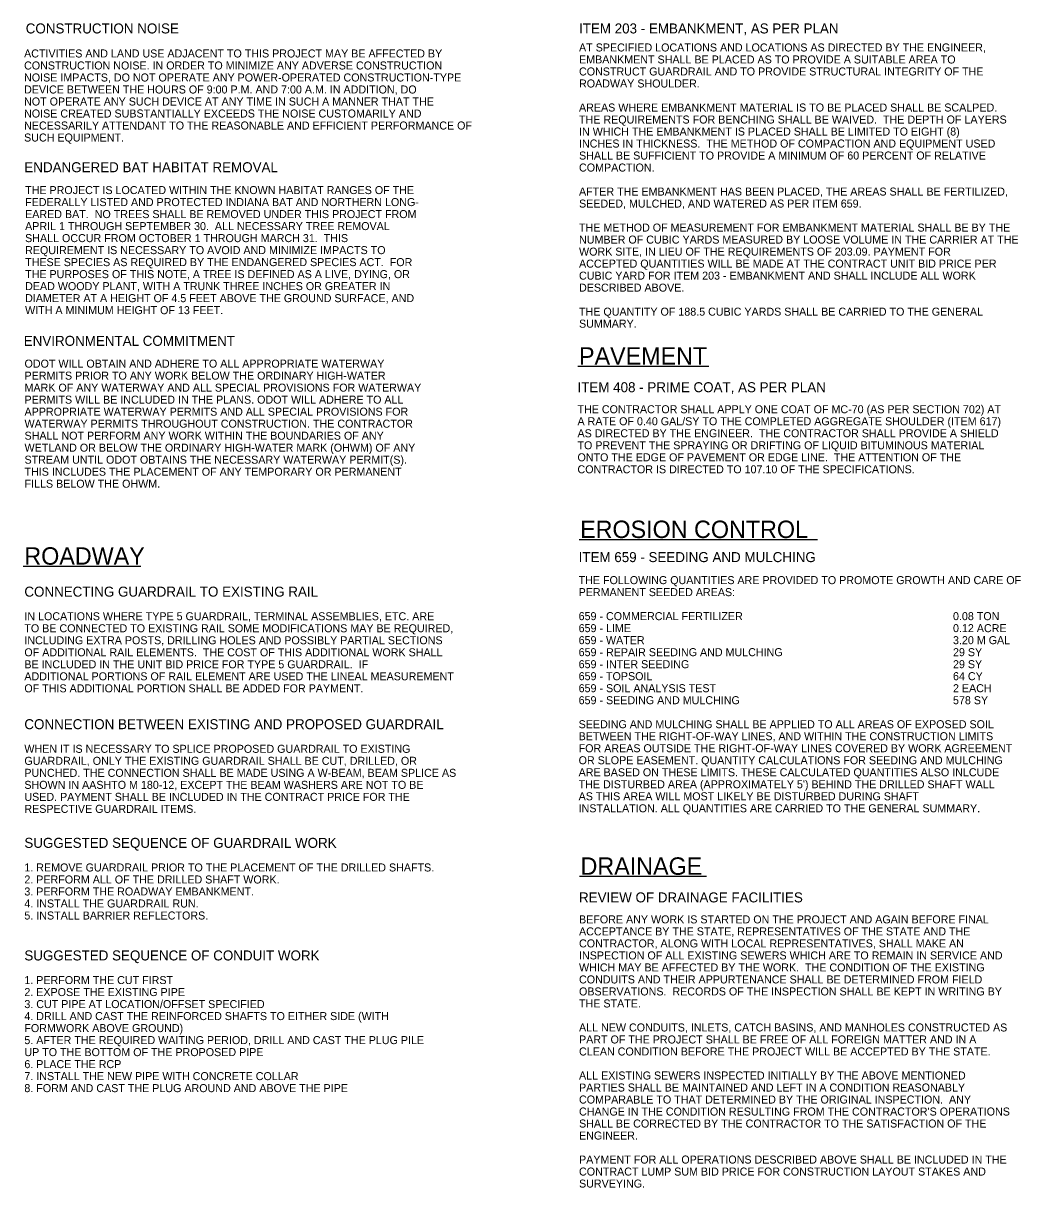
# Model space of a CAD drawing. Extents: x 0 to 43.5, y 0 to 44.1.
# Drawn here: x 12.78 to 30.22, y 23.75 to 44.11 of the extents above; entities that cross this region are included whole.
import ezdxf

# ---------------------------------------------------------------- set-up
doc = ezdxf.new("R2010")
doc.units = 0
doc.layers.add('Default', color=7, linetype='Continuous')
doc.layers.add('TX_P_1', color=7, linetype='Continuous')

msp = doc.modelspace()

# ---------------------------------------------------------------- linework, layer by layer
at = {"layer": 'Default'}
for p, q in [((22.481, 38.118), (24.771, 38.118)), ((22.5, 35.085), (26.668, 35.085)), ((12.781, 34.619), (14.836, 34.619)), ((22.508, 29.196), (24.729, 29.196))]:
    msp.add_line(p, q, dxfattribs=at)

# ---------------------------------------------------------------- texts
at = {"layer": 'TX_P_1'}
for s, height, p in [('CONSTRUCTION NOISE', 0.175, (12.824, 43.934)), ('ITEM 203 - EMBANKMENT, AS PER PLAN', 0.175, (22.5, 43.934)), ('ACTIVITIES AND LAND USE ADJACENT TO THIS PROJECT MAY BE AFFECTED BY ', 0.14, (12.795, 43.514)), ('AT SPECIFIED LOCATIONS AND LOCATIONS AS DIRECTED BY THE ENGINEER, ', 0.14, (22.5, 43.619)), ('CONSTRUCTION NOISE. IN ORDER TO MINIMIZE ANY ADVERSE CONSTRUCTION ', 0.14, (12.795, 43.304)), ('EMBANKMENT SHALL BE PLACED AS TO PROVIDE A SUITABLE AREA TO ', 0.14, (22.5, 43.409)), ('NOISE IMPACTS, DO NOT OPERATE ANY POWER-OPERATED CONSTRUCTION-TYPE ', 0.14, (12.795, 43.094)), ('CONSTRUCT GUARDRAIL AND TO PROVIDE STRUCTURAL INTEGRITY OF THE ', 0.14, (22.5, 43.199)), ('DEVICE BETWEEN THE HOURS OF 9:00 P.M. AND 7:00 A.M. IN ADDITION, DO ', 0.14, (12.795, 42.884)), ('ROADWAY SHOULDER.', 0.14, (22.5, 42.989)), ('NOT OPERATE ANY SUCH DEVICE AT ANY TIME IN SUCH A MANNER THAT THE ', 0.14, (12.795, 42.674)), ('NOISE CREATED SUBSTANTIALLY EXCEEDS THE NOISE CUSTOMARILY AND ', 0.14, (12.795, 42.464)), ('AREAS WHERE EMBANKMENT MATERIAL IS TO BE PLACED SHALL BE SCALPED. ', 0.14, (22.5, 42.569)), ('NECESSARILY ATTENDANT TO THE REASONABLE AND EFFICIENT PERFORMANCE OF ', 0.14, (12.795, 42.254)), ('THE REQUIREMENTS FOR BENCHING SHALL BE WAIVED.  THE DEPTH OF LAYERS ', 0.14, (22.5, 42.359)), ('SUCH EQUIPMENT.', 0.14, (12.795, 42.044)), ('IN WHICH THE EMBANKMENT IS PLACED SHALL BE LIMITED TO EIGHT (8) ', 0.14, (22.5, 42.149)), ('INCHES IN THICKNESS.  THE METHOD OF COMPACTION AND EQUIPMENT USED ', 0.14, (22.5, 41.939)), ('SHALL BE SUFFICIENT TO PROVIDE A MINIMUM OF 60 PERCENT OF RELATIVE ', 0.14, (22.5, 41.729)), ('ENDANGERED BAT HABITAT REMOVAL', 0.175, (12.8, 41.507)), ('COMPACTION.', 0.14, (22.5, 41.519)), ('THE PROJECT IS LOCATED WITHIN THE KNOWN HABITAT RANGES OF THE ', 0.14, (12.813, 41.125)), ('AFTER THE EMBANKMENT HAS BEEN PLACED, THE AREAS SHALL BE FERTILIZED, ', 0.14, (22.5, 41.099)), ('FEDERALLY LISTED AND PROTECTED INDIANA BAT AND NORTHERN LONG-', 0.14, (12.813, 40.915)), ('SEEDED, MULCHED, AND WATERED AS PER ITEM 659. ', 0.14, (22.5, 40.889)), ('EARED BAT.  NO TREES SHALL BE REMOVED UNDER THIS PROJECT FROM ', 0.14, (12.813, 40.705)), ('APRIL 1 THROUGH SEPTEMBER 30.  ALL NECESSARY TREE REMOVAL ', 0.14, (12.813, 40.495)), ('THE METHOD OF MEASUREMENT FOR EMBANKMENT MATERIAL SHALL BE BY THE ', 0.14, (22.5, 40.469)), ('SHALL OCCUR FROM OCTOBER 1 THROUGH MARCH 31.  THIS ', 0.14, (12.813, 40.285)), ('NUMBER OF CUBIC YARDS MEASURED BY LOOSE VOLUME IN THE CARRIER AT THE ', 0.14, (22.5, 40.259)), ('REQUIREMENT IS NECESSARY TO AVOID AND MINIMIZE IMPACTS TO ', 0.14, (12.813, 40.075)), ('WORK SITE, IN LIEU OF THE REQUIREMENTS OF 203.09. PAYMENT FOR ', 0.14, (22.5, 40.049)), ('THESE SPECIES AS REQUIRED BY THE ENDANGERED SPECIES ACT.  FOR ', 0.14, (12.813, 39.865)), ('ACCEPTED QUANTITIES WILL BE MADE AT THE CONTRACT UNIT BID PRICE PER ', 0.14, (22.5, 39.839)), ('THE PURPOSES OF THIS NOTE, A TREE IS DEFINED AS A LIVE, DYING, OR ', 0.14, (12.813, 39.655)), ('CUBIC YARD FOR ITEM 203 - EMBANKMENT AND SHALL INCLUDE ALL WORK ', 0.14, (22.5, 39.629)), ('DEAD WOODY PLANT, WITH A TRUNK THREE INCHES OR GREATER IN ', 0.14, (12.813, 39.445)), ('DESCRIBED ABOVE.', 0.14, (22.5, 39.419)), ('DIAMETER AT A HEIGHT OF 4.5 FEET ABOVE THE GROUND SURFACE, AND ', 0.14, (12.813, 39.235)), ('WITH A MINIMUM HEIGHT OF 13 FEET.', 0.14, (12.813, 39.025)), ('THE QUANTITY OF 188.5 CUBIC YARDS SHALL BE CARRIED TO THE GENERAL ', 0.14, (22.5, 38.999)), ('SUMMARY.', 0.14, (22.5, 38.789)), ('ENVIRONMENTAL COMMITMENT', 0.175, (12.79, 38.471)), ('PAVEMENT', 0.3047, (22.5, 38.142)), ('ODOT WILL OBTAIN AND ADHERE TO ALL APPROPRIATE WATERWAY ', 0.14, (12.803, 38.09)), ('PERMITS PRIOR TO ANY WORK BELOW THE ORDINARY HIGH-WATER ', 0.14, (12.803, 37.88)), ('MARK OF ANY WATERWAY AND ALL SPECIAL PROVISIONS FOR WATERWAY ', 0.14, (12.803, 37.67)), ('ITEM 408 - PRIME COAT, AS PER PLAN', 0.175, (22.473, 37.66)), ('PERMITS WILL BE INCLUDED IN THE PLANS. ODOT WILL ADHERE TO ALL ', 0.14, (12.803, 37.46)), ('APPROPRIATE WATERWAY PERMITS AND ALL SPECIAL PROVISIONS FOR ', 0.14, (12.803, 37.25)), ('THE CONTRACTOR SHALL APPLY ONE COAT OF MC-70 (AS PER SECTION 702) AT ', 0.14, (22.473, 37.292)), ('WATERWAY PERMITS THROUGHOUT CONSTRUCTION. THE CONTRACTOR ', 0.14, (12.803, 37.04)), ('A RATE OF 0.40 GAL/SY TO THE COMPLETED AGGREGATE SHOULDER (ITEM 617) ', 0.14, (22.473, 37.082)), ('SHALL NOT PERFORM ANY WORK WITHIN THE BOUNDARIES OF ANY ', 0.14, (12.803, 36.83)), ('AS DIRECTED BY THE ENGINEER.  THE CONTRACTOR SHALL PROVIDE A SHIELD ', 0.14, (22.473, 36.872)), ('WETLAND OR BELOW THE ORDINARY HIGH-WATER MARK (OHWM) OF ANY ', 0.14, (12.803, 36.62)), ('TO PREVENT THE SPRAYING OR DRIFTING OF LIQUID BITUMINOUS MATERIAL ', 0.14, (22.473, 36.662)), ('STREAM UNTIL ODOT OBTAINS THE NECESSARY WATERWAY PERMIT(S). ', 0.14, (12.803, 36.41)), ('ONTO THE EDGE OF PAVEMENT OR EDGE LINE.  THE ATTENTION OF THE ', 0.14, (22.473, 36.452)), ('THIS INCLUDES THE PLACEMENT OF ANY TEMPORARY OR PERMANENT ', 0.14, (12.803, 36.2)), ('CONTRACTOR IS DIRECTED TO 107.10 OF THE SPECIFICATIONS.', 0.14, (22.473, 36.242)), ('FILLS BELOW THE OHWM.', 0.14, (12.803, 35.99)), ('EROSION CONTROL', 0.30475, (22.519, 35.11)), ('ROADWAY', 0.3047, (12.8, 34.644)), ('ITEM 659 - SEEDING AND MULCHING', 0.175, (22.493, 34.689)), ('THE FOLLOWING QUANTITIES ARE PROVIDED TO PROMOTE GROWTH AND CARE OF ', 0.14, (22.493, 34.304)), ('CONNECTING GUARDRAIL TO EXISTING RAIL', 0.175, (12.8, 34.085)), ('PERMANENT SEEDED AREAS:', 0.14, (22.493, 34.094)), ('IN LOCATIONS WHERE TYPE 5 GUARDRAIL, TERMINAL ASSEMBLIES, ETC. ARE ', 0.14, (12.8, 33.672)), ('659 - COMMERCIAL FERTILIZER', 0.14, (22.493, 33.674)), ('0.08 TON', 0.14, (29.04, 33.674)), ('TO BE CONNECTED TO EXISTING RAIL SOME MODIFICATIONS MAY BE REQUIRED, ', 0.14, (12.8, 33.462)), ('659 - LIME', 0.14, (22.493, 33.464)), ('0.12 ACRE', 0.14, (29.04, 33.464)), ('659 - WATER', 0.14, (22.493, 33.254)), ('3.20 M GAL', 0.14, (29.04, 33.254)), ('INCLUDING EXTRA POSTS, DRILLING HOLES AND POSSIBLY PARTIAL SECTIONS ', 0.14, (12.8, 33.252)), ('OF ADDITIONAL RAIL ELEMENTS.  THE COST OF THIS ADDITIONAL WORK SHALL ', 0.14, (12.8, 33.042)), ('659 - REPAIR SEEDING AND MULCHING', 0.14, (22.493, 33.044)), ('29 SY', 0.14, (29.04, 33.044)), ('BE INCLUDED IN THE UNIT BID PRICE FOR TYPE 5 GUARDRAIL.  IF ', 0.14, (12.8, 32.832)), ('659 - INTER SEEDING', 0.14, (22.493, 32.834)), ('29 SY', 0.14, (29.04, 32.834)), ('ADDITIONAL PORTIONS OF RAIL ELEMENT ARE USED THE LINEAL MEASUREMENT ', 0.14, (12.8, 32.622)), ('659 - TOPSOIL', 0.14, (22.493, 32.624)), ('64 CY', 0.14, (29.04, 32.624)), ('OF THIS ADDITIONAL PORTION SHALL BE ADDED FOR PAYMENT.', 0.14, (12.8, 32.412)), ('659 - SOIL ANALYSIS TEST', 0.14, (22.493, 32.414)), ('2 EACH', 0.14, (29.04, 32.414)), ('659 - SEEDING AND MULCHING', 0.14, (22.493, 32.204)), ('578 SY', 0.14, (29.04, 32.204)), ('CONNECTION BETWEEN EXISTING AND PROPOSED GUARDRAIL', 0.175, (12.8, 31.767)), ('SEEDING AND MULCHING SHALL BE APPLIED TO ALL AREAS OF EXPOSED SOIL ', 0.14, (22.493, 31.784)), ('BETWEEN THE RIGHT-OF-WAY LINES, AND WITHIN THE CONSTRUCTION LIMITS ', 0.14, (22.493, 31.574)), ('WHEN IT IS NECESSARY TO SPLICE PROPOSED GUARDRAIL TO EXISTING ', 0.14, (12.8, 31.354)), ('FOR AREAS OUTSIDE THE RIGHT-OF-WAY LINES COVERED BY WORK AGREEMENT ', 0.14, (22.493, 31.364)), ('GUARDRAIL, ONLY THE EXISTING GUARDRAIL SHALL BE CUT, DRILLED, OR ', 0.14, (12.8, 31.144)), ('OR SLOPE EASEMENT. QUANTITY CALCULATIONS FOR SEEDING AND MULCHING ', 0.14, (22.493, 31.154)), ('PUNCHED. THE CONNECTION SHALL BE MADE USING A W-BEAM, BEAM SPLICE AS ', 0.14, (12.8, 30.934)), ('ARE BASED ON THESE LIMITS. THESE CALCULATED QUANTITIES ALSO INLCUDE ', 0.14, (22.493, 30.944)), ('SHOWN IN AASHTO M 180-12, EXCEPT THE BEAM WASHERS ARE NOT TO BE ', 0.14, (12.8, 30.724)), ("THE DISTURBED AREA (APPROXIMATELY 5') BEHIND THE DRILLED SHAFT WALL ", 0.14, (22.493, 30.734)), ('USED. PAYMENT SHALL BE INCLUDED IN THE CONTRACT PRICE FOR THE ', 0.14, (12.8, 30.514)), ('AS THIS AREA WILL MOST LIKELY BE DISTURBED DURING SHAFT ', 0.14, (22.493, 30.524)), ('RESPECTIVE GUARDRAIL ITEMS.', 0.14, (12.8, 30.304)), ('INSTALLATION. ALL QUANTITIES ARE CARRIED TO THE GENERAL SUMMARY.', 0.14, (22.493, 30.314)), ('SUGGESTED SEQUENCE OF GUARDRAIL WORK', 0.175, (12.8, 29.692)), ('DRAINAGE', 0.3047, (22.527, 29.221)), ('1. REMOVE GUARDRAIL PRIOR TO THE PLACEMENT OF THE DRILLED SHAFTS.', 0.14, (12.8, 29.279)), ('2. PERFORM ALL OF THE DRILLED SHAFT WORK. ', 0.14, (12.8, 29.069)), ('3. PERFORM THE ROADWAY EMBANKMENT.  ', 0.14, (12.8, 28.859)), ('REVIEW OF DRAINAGE FACILITIES', 0.175, (22.5, 28.738)), ('4. INSTALL THE GUARDRAIL RUN. ', 0.14, (12.8, 28.649)), ('5. INSTALL BARRIER REFLECTORS.', 0.14, (12.8, 28.439)), ('BEFORE ANY WORK IS STARTED ON THE PROJECT AND AGAIN BEFORE FINAL ', 0.14, (22.5, 28.371)), ('ACCEPTANCE BY THE STATE, REPRESENTATIVES OF THE STATE AND THE ', 0.14, (22.5, 28.161)), ('SUGGESTED SEQUENCE OF CONDUIT WORK', 0.175, (12.8, 27.723)), ('CONTRACTOR, ALONG WITH LOCAL REPRESENTATIVES, SHALL MAKE AN ', 0.14, (22.5, 27.951)), ('INSPECTION OF ALL EXISTING SEWERS WHICH ARE TO REMAIN IN SERVICE AND ', 0.14, (22.5, 27.741)), ('WHICH MAY BE AFFECTED BY THE WORK.  THE CONDITION OF THE EXISTING ', 0.14, (22.5, 27.531)), ('1. PERFORM THE CUT FIRST', 0.14, (12.8, 27.31)), ('CONDUITS AND THEIR APPURTENANCE SHALL BE DETERMINED FROM FIELD ', 0.14, (22.5, 27.321)), ('2. EXPOSE THE EXISTING PIPE ', 0.14, (12.8, 27.1)), ('OBSERVATIONS.  RECORDS OF THE INSPECTION SHALL BE KEPT IN WRITING BY ', 0.14, (22.5, 27.111)), ('3. CUT PIPE AT LOCATION/OFFSET SPECIFIED ', 0.14, (12.8, 26.89)), ('THE STATE.', 0.14, (22.5, 26.901)), ('4. DRILL AND CAST THE REINFORCED SHAFTS TO EITHER SIDE (WITH ', 0.14, (12.8, 26.68)), ('FORMWORK ABOVE GROUND)', 0.14, (12.8, 26.47)), ('ALL NEW CONDUITS, INLETS, CATCH BASINS, AND MANHOLES CONSTRUCTED AS  ', 0.14, (22.5, 26.481)), ('5. AFTER THE REQUIRED WAITING PERIOD, DRILL AND CAST THE PLUG PILE ', 0.14, (12.8, 26.26)), ('PART OF THE PROJECT SHALL BE FREE OF ALL FOREIGN MATTER AND IN A ', 0.14, (22.5, 26.271)), ('UP TO THE BOTTOM OF THE PROPOSED PIPE', 0.14, (12.8, 26.05)), ('CLEAN CONDITION BEFORE THE PROJECT WILL BE ACCEPTED BY THE STATE.', 0.14, (22.5, 26.061)), ('6. PLACE THE RCP', 0.14, (12.8, 25.84)), ('7. INSTALL THE NEW PIPE WITH CONCRETE COLLAR', 0.14, (12.8, 25.63)), ('ALL EXISTING SEWERS INSPECTED INITIALLY BY THE ABOVE MENTIONED ', 0.14, (22.5, 25.641)), ('8. FORM AND CAST THE PLUG AROUND AND ABOVE THE PIPE', 0.14, (12.8, 25.42)), ('PARTIES SHALL BE MAINTAINED AND LEFT IN A CONDITION REASONABLY ', 0.14, (22.5, 25.431)), ('COMPARABLE TO THAT DETERMINED BY THE ORIGINAL INSPECTION.  ANY ', 0.14, (22.5, 25.221)), ("CHANGE IN THE CONDITION RESULTING FROM THE CONTRACTOR'S OPERATIONS ", 0.14, (22.5, 25.011)), ('SHALL BE CORRECTED BY THE CONTRACTOR TO THE SATISFACTION OF THE ', 0.14, (22.5, 24.801)), ('ENGINEER.', 0.14, (22.5, 24.591)), ('PAYMENT FOR ALL OPERATIONS DESCRIBED ABOVE SHALL BE INCLUDED IN THE ', 0.14, (22.5, 24.171)), ('CONTRACT LUMP SUM BID PRICE FOR CONSTRUCTION LAYOUT STAKES AND ', 0.14, (22.5, 23.961)), ('SURVEYING.', 0.14, (22.5, 23.751))]:
    msp.add_text(s, height=height, dxfattribs=at).set_placement(p)

doc.saveas('drawing.dxf')
